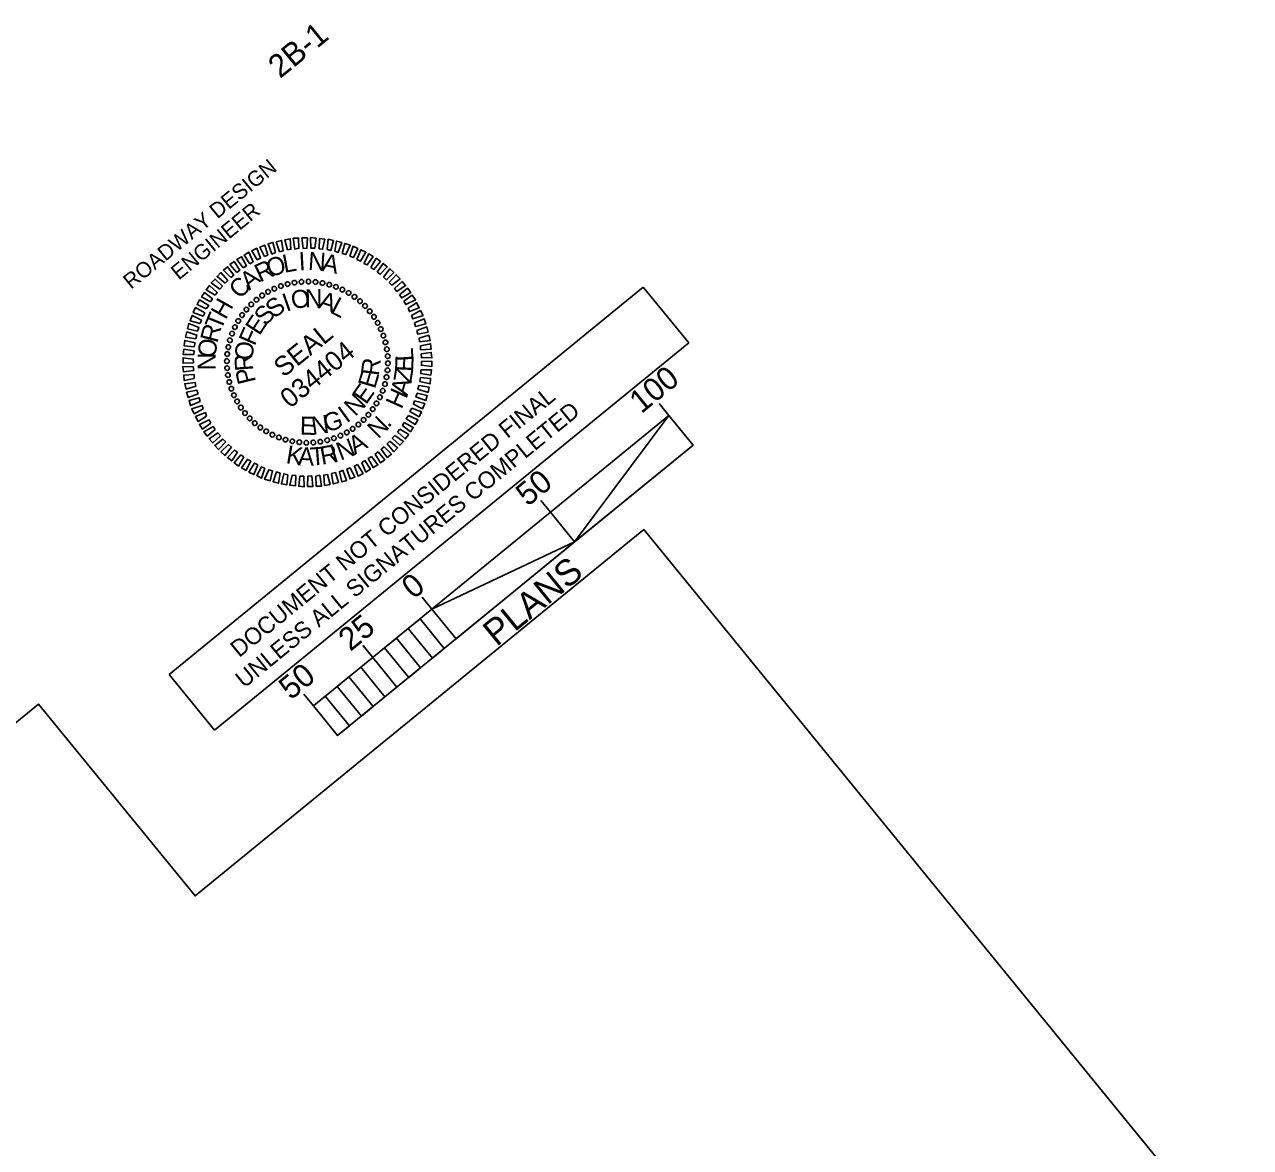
# Model space of a CAD drawing. Extents: x 1528967 to 2322919, y 597128 to 795043.
# Drawn here: x 2322186.2 to 2322586.9, y 598460.6 to 598827.5 of the extents above; entities that cross this region are included whole.
import ezdxf

# ---------------------------------------------------------------- set-up
doc = ezdxf.new("R2010")
doc.units = 0
for name, color, linetype in [('Sheet Data Field CELL', 7, 'Continuous'), ('Sheet Plan CELL', 7, 'Continuous'), ('Sheet Sticker Exception Certification CELL', 7, 'Continuous'), ('Sheet Title CELL', 7, 'Continuous')]:
    doc.layers.add(name, color=color, linetype=linetype)

msp = doc.modelspace()

# ---------------------------------------------------------------- linework, layer by layer
at = {"layer": 'Sheet Data Field CELL'}
for p, q in [((2322272.18, 598742.73), (2322272.18, 598742.73)), ((2322274.42, 598743.25), (2322274.42, 598743.25)), ((2322276.71, 598743.47), (2322276.71, 598743.47)), ((2322279.03, 598743.57), (2322279.03, 598743.57)), ((2322281.29, 598743.42), (2322281.29, 598743.42)), ((2322283.61, 598743.12), (2322283.61, 598743.12)), ((2322285.79, 598742.56), (2322285.79, 598742.56)), ((2322263.87, 598738.99), (2322263.87, 598738.99)), ((2322265.83, 598740.17), (2322265.83, 598740.17)), ((2322267.81, 598741.23), (2322267.81, 598741.23)), ((2322269.97, 598742.09), (2322269.97, 598742.09)), ((2322288, 598741.82), (2322288, 598741.82)), ((2322290.12, 598740.93), (2322290.12, 598740.93)), ((2322292.12, 598739.87), (2322292.12, 598739.87)), ((2322294.02, 598738.6), (2322294.02, 598738.6)), ((2322260.27, 598736.09), (2322260.27, 598736.09)), ((2322262, 598737.62), (2322262, 598737.62)), ((2322295.84, 598737.11), (2322295.84, 598737.11)), ((2322297.53, 598735.59), (2322297.53, 598735.59)), ((2322255.99, 598730.68), (2322255.99, 598730.68)), ((2322257.26, 598732.58), (2322257.26, 598732.58)), ((2322258.75, 598734.39), (2322258.75, 598734.39)), ((2322299.06, 598733.86), (2322299.06, 598733.86)), ((2322300.43, 598731.99), (2322300.43, 598731.99)), ((2322254.04, 598726.56), (2322254.04, 598726.56)), ((2322254.93, 598728.68), (2322254.93, 598728.68)), ((2322301.61, 598730.03), (2322301.61, 598730.03)), ((2322302.67, 598728.05), (2322302.67, 598728.05)), ((2322253.3, 598724.35), (2322253.3, 598724.35)), ((2322303.54, 598725.89), (2322303.54, 598725.89)), ((2322304.17, 598723.68), (2322304.17, 598723.68)), ((2322252.44, 598719.84), (2322252.44, 598719.84)), ((2322252.74, 598722.16), (2322252.74, 598722.16)), ((2322304.69, 598721.44), (2322304.69, 598721.44)), ((2322304.91, 598719.15), (2322304.91, 598719.15)), ((2322252.29, 598717.59), (2322252.29, 598717.59)), ((2322252.39, 598715.27), (2322252.39, 598715.27)), ((2322304.86, 598714.57), (2322304.86, 598714.57)), ((2322305.01, 598716.83), (2322305.01, 598716.83)), ((2322252.61, 598712.98), (2322252.61, 598712.98)), ((2322253.13, 598710.74), (2322253.13, 598710.74)), ((2322304.56, 598712.25), (2322304.56, 598712.25)), ((2322253.77, 598708.53), (2322253.77, 598708.53)), ((2322254.63, 598706.37), (2322254.63, 598706.37)), ((2322303.26, 598707.86), (2322303.26, 598707.86)), ((2322304, 598710.07), (2322304, 598710.07)), ((2322255.69, 598704.38), (2322255.69, 598704.38)), ((2322256.87, 598702.42), (2322256.87, 598702.42)), ((2322301.32, 598703.74), (2322301.32, 598703.74)), ((2322302.38, 598705.74), (2322302.38, 598705.74)), ((2322258.24, 598700.56), (2322258.24, 598700.56)), ((2322259.77, 598698.83), (2322259.77, 598698.83)), ((2322298.55, 598700.02), (2322298.55, 598700.02)), ((2322300.04, 598701.84), (2322300.04, 598701.84)), ((2322261.47, 598697.31), (2322261.47, 598697.31)), ((2322263.28, 598695.82), (2322263.28, 598695.82)), ((2322265.18, 598694.54), (2322265.18, 598694.54)), ((2322293.44, 598695.43), (2322293.44, 598695.43)), ((2322295.3, 598696.8), (2322295.3, 598696.8)), ((2322297.03, 598698.33), (2322297.03, 598698.33)), ((2322267.18, 598693.48), (2322267.18, 598693.48)), ((2322269.3, 598692.6), (2322269.3, 598692.6)), ((2322271.51, 598691.86), (2322271.51, 598691.86)), ((2322273.7, 598691.3), (2322273.7, 598691.3)), ((2322276.02, 598691), (2322276.02, 598691)), ((2322278.27, 598690.85), (2322278.27, 598690.85)), ((2322280.59, 598690.95), (2322280.59, 598690.95)), ((2322282.88, 598691.17), (2322282.88, 598691.17)), ((2322285.12, 598691.69), (2322285.12, 598691.69)), ((2322287.33, 598692.32), (2322287.33, 598692.32)), ((2322289.49, 598693.19), (2322289.49, 598693.19)), ((2322291.48, 598694.25), (2322291.48, 598694.25)), ((2322358.08, 598668.17), (2322354.92, 598672.03)), ((2322299.99, 598620.72), (2322296.83, 598624.59)), ((2322280.62, 598604.92), (2322277.46, 598608.78))]:
    msp.add_line(p, q, dxfattribs=at)
for points in [[(2322264.63, 598751.74), (2322263.13, 598754.73), (2322264.71, 598755.38), (2322265.71, 598752.17)], [(2322267.04, 598752.54), (2322265.83, 598755.84), (2322267.36, 598756.31), (2322268.2, 598753.04)], [(2322269.49, 598753.3), (2322268.49, 598756.51), (2322270.21, 598757), (2322270.74, 598753.61)], [(2322272.11, 598753.94), (2322271.26, 598757.14), (2322273.04, 598757.47), (2322273.28, 598754.1)], [(2322274.59, 598754.18), (2322274.03, 598757.69), (2322275.78, 598757.73), (2322275.88, 598754.45)], [(2322277.25, 598754.37), (2322276.87, 598757.82), (2322278.65, 598757.82), (2322278.48, 598754.45)], [(2322279.82, 598754.41), (2322279.7, 598757.89), (2322281.48, 598757.74), (2322281.09, 598754.46)], [(2322282.45, 598754.23), (2322282.58, 598757.57), (2322284.35, 598757.42), (2322283.59, 598754.1)], [(2322285.07, 598753.98), (2322285.39, 598757.34), (2322287.14, 598756.97), (2322286.31, 598753.65)], [(2322287.59, 598753.43), (2322288.13, 598756.77), (2322289.88, 598756.25), (2322288.72, 598753.08)], [(2322290.02, 598752.67), (2322290.86, 598755.99), (2322292.64, 598755.43), (2322291.26, 598752.34)], [(2322292.56, 598751.79), (2322293.61, 598755.09), (2322295.18, 598754.29), (2322293.68, 598751.43)], [(2322257.66, 598748.04), (2322255.62, 598750.78), (2322257.14, 598751.65), (2322258.76, 598748.69)], [(2322259.85, 598749.34), (2322258.04, 598752.21), (2322259.54, 598753.13), (2322260.92, 598750.04)], [(2322262.27, 598750.63), (2322260.47, 598753.57), (2322262.1, 598754.4), (2322263.28, 598751.14)], [(2322294.81, 598750.74), (2322296.16, 598753.94), (2322297.77, 598753.1), (2322295.96, 598750.2)], [(2322297.13, 598749.47), (2322298.69, 598752.58), (2322300.18, 598751.71), (2322298.24, 598748.97)], [(2322299.4, 598748.09), (2322301.18, 598751.18), (2322302.54, 598750.06), (2322300.39, 598747.49)], [(2322251.76, 598742.98), (2322249.16, 598745.17), (2322250.38, 598746.48), (2322252.62, 598743.91)], [(2322253.6, 598744.88), (2322251.19, 598747.31), (2322252.55, 598748.39), (2322254.59, 598745.65)], [(2322255.55, 598746.46), (2322253.35, 598749.07), (2322254.71, 598750.14), (2322256.55, 598747.24)], [(2322301.5, 598746.57), (2322303.38, 598749.47), (2322304.77, 598748.31), (2322302.45, 598745.94)], [(2322303.49, 598744.95), (2322305.62, 598747.72), (2322306.89, 598746.46), (2322304.46, 598744.13)], [(2322250.04, 598741.11), (2322247.24, 598743.14), (2322248.46, 598744.37), (2322250.9, 598742.05)], [(2322305.36, 598743.24), (2322307.69, 598745.76), (2322308.92, 598744.46), (2322306.25, 598742.34)], [(2322307.09, 598741.27), (2322309.59, 598743.59), (2322310.74, 598742.23), (2322307.9, 598740.31)], [(2322247.01, 598736.9), (2322244.06, 598738.52), (2322245, 598739.93), (2322247.62, 598737.89)], [(2322248.49, 598739.05), (2322245.52, 598740.86), (2322246.64, 598742.29), (2322249.17, 598739.96)], [(2322308.74, 598739.23), (2322311.42, 598741.35), (2322312.45, 598739.96), (2322309.48, 598738.2)], [(2322310.17, 598737.14), (2322312.94, 598739.07), (2322313.93, 598737.57), (2322310.78, 598736.01)], [(2322244.54, 598732.27), (2322241.36, 598733.43), (2322242.13, 598735.04), (2322245.12, 598733.37)], [(2322245.59, 598734.6), (2322242.59, 598736.04), (2322243.38, 598737.54), (2322246.39, 598735.69)], [(2322311.58, 598734.82), (2322314.33, 598736.6), (2322315.2, 598735.01), (2322311.97, 598733.71)], [(2322243.63, 598729.85), (2322240.32, 598730.76), (2322241.02, 598732.45), (2322243.99, 598730.97)], [(2322312.68, 598732.46), (2322315.61, 598734.04), (2322316.45, 598732.48), (2322313.08, 598731.35)], [(2322313.71, 598730.03), (2322316.8, 598731.41), (2322317.33, 598729.73), (2322313.98, 598728.82)], [(2322242.21, 598724.87), (2322238.86, 598725.33), (2322239.23, 598727.09), (2322242.53, 598726.03)], [(2322242.72, 598727.36), (2322239.51, 598728.15), (2322239.9, 598729.79), (2322243.19, 598728.58)], [(2322314.4, 598727.59), (2322317.66, 598728.77), (2322318.11, 598727.02), (2322314.74, 598726.37)], [(2322241.66, 598722.27), (2322238.41, 598722.54), (2322238.55, 598724.32), (2322241.95, 598723.47)], [(2322315.16, 598725.07), (2322318.29, 598726), (2322318.74, 598724.25), (2322315.32, 598723.9)], [(2322315.65, 598722.53), (2322318.91, 598723.23), (2322319.06, 598721.43), (2322315.62, 598721.27)], [(2322241.41, 598717.04), (2322238, 598716.84), (2322238, 598718.63), (2322241.36, 598718.24)], [(2322241.52, 598719.75), (2322238.09, 598719.66), (2322238.31, 598721.43), (2322241.62, 598720.93)], [(2322315.81, 598719.91), (2322319.12, 598720.38), (2322319.34, 598718.58), (2322315.93, 598718.71)], [(2322241.49, 598714.5), (2322238.18, 598714.04), (2322237.96, 598715.84), (2322241.37, 598715.7)], [(2322315.78, 598714.67), (2322319.21, 598714.75), (2322318.99, 598712.99), (2322315.68, 598713.49)], [(2322315.89, 598717.38), (2322319.3, 598717.58), (2322319.3, 598715.79), (2322315.94, 598716.18)], [(2322241.65, 598711.88), (2322238.39, 598711.19), (2322238.24, 598712.99), (2322241.68, 598713.15)], [(2322242.14, 598709.35), (2322239.01, 598708.42), (2322238.56, 598710.17), (2322241.98, 598710.52)], [(2322315.64, 598712.15), (2322318.9, 598711.88), (2322318.75, 598710.1), (2322315.36, 598710.94)], [(2322242.9, 598706.83), (2322239.64, 598705.65), (2322239.19, 598707.4), (2322242.56, 598708.05)], [(2322314.58, 598707.06), (2322317.8, 598706.27), (2322317.4, 598704.63), (2322314.11, 598705.84)], [(2322315.09, 598709.55), (2322318.44, 598709.09), (2322318.07, 598707.33), (2322314.77, 598708.39)], [(2322243.59, 598704.39), (2322240.5, 598703.01), (2322239.97, 598704.69), (2322243.32, 598705.6)], [(2322244.62, 598701.96), (2322241.69, 598700.38), (2322240.86, 598701.94), (2322244.23, 598703.07)], [(2322313.67, 598704.57), (2322316.98, 598703.66), (2322316.28, 598701.97), (2322313.32, 598703.44)], [(2322245.72, 598699.59), (2322242.97, 598697.81), (2322242.1, 598699.41), (2322245.33, 598700.71)], [(2322247.13, 598697.28), (2322244.36, 598695.35), (2322243.37, 598696.85), (2322246.52, 598698.41)], [(2322311.71, 598699.82), (2322314.72, 598698.38), (2322313.92, 598696.88), (2322310.91, 598698.73)], [(2322312.76, 598702.15), (2322315.94, 598700.99), (2322315.17, 598699.38), (2322312.18, 598701.05)], [(2322248.56, 598695.19), (2322245.89, 598693.07), (2322244.85, 598694.46), (2322247.82, 598696.22)], [(2322308.81, 598695.37), (2322311.78, 598693.56), (2322310.66, 598692.13), (2322308.14, 598694.46)], [(2322310.29, 598697.52), (2322313.24, 598695.89), (2322312.31, 598694.48), (2322309.68, 598696.53)], [(2322250.21, 598693.15), (2322247.71, 598690.83), (2322246.56, 598692.19), (2322249.4, 598694.11)], [(2322251.95, 598691.18), (2322249.61, 598688.66), (2322248.38, 598689.95), (2322251.05, 598692.08)], [(2322305.54, 598691.44), (2322308.15, 598689.25), (2322306.92, 598687.93), (2322304.68, 598690.5)], [(2322307.26, 598693.3), (2322310.07, 598691.28), (2322308.85, 598690.04), (2322306.4, 598692.37)], [(2322253.81, 598689.46), (2322251.68, 598686.7), (2322250.41, 598687.96), (2322252.84, 598690.29)], [(2322255.8, 598687.85), (2322253.92, 598684.95), (2322252.53, 598686.11), (2322254.85, 598688.48)], [(2322257.91, 598686.33), (2322256.12, 598683.24), (2322254.76, 598684.36), (2322256.91, 598686.93)], [(2322299.64, 598686.38), (2322301.69, 598683.64), (2322300.16, 598682.76), (2322298.55, 598685.73)], [(2322301.75, 598687.96), (2322303.95, 598685.35), (2322302.59, 598684.27), (2322300.75, 598687.18)], [(2322303.7, 598689.54), (2322306.11, 598687.11), (2322304.75, 598686.03), (2322302.71, 598688.77)], [(2322260.17, 598684.95), (2322258.61, 598681.84), (2322257.12, 598682.71), (2322259.06, 598685.45)], [(2322262.49, 598683.68), (2322261.14, 598680.47), (2322259.54, 598681.32), (2322261.34, 598684.22)], [(2322264.75, 598682.63), (2322263.69, 598679.33), (2322262.12, 598680.13), (2322263.62, 598682.99)], [(2322292.67, 598682.68), (2322294.17, 598679.69), (2322292.59, 598679.04), (2322291.59, 598682.25)], [(2322295.03, 598683.79), (2322296.84, 598680.85), (2322295.2, 598680.01), (2322294.02, 598683.28)], [(2322297.45, 598685.08), (2322299.26, 598682.21), (2322297.77, 598681.29), (2322296.39, 598684.38)], [(2322267.28, 598681.75), (2322266.44, 598678.43), (2322264.66, 598678.99), (2322266.04, 598682.08)], [(2322269.71, 598680.99), (2322269.17, 598677.65), (2322267.43, 598678.16), (2322268.58, 598681.34)], [(2322272.23, 598680.44), (2322271.91, 598677.08), (2322270.16, 598677.45), (2322270.99, 598680.77)], [(2322274.85, 598680.19), (2322274.72, 598676.85), (2322272.95, 598676.99), (2322273.71, 598680.32)], [(2322277.48, 598680), (2322277.6, 598676.53), (2322275.83, 598676.68), (2322276.21, 598679.96)], [(2322280.05, 598680.05), (2322280.44, 598676.59), (2322278.65, 598676.59), (2322278.82, 598679.97)], [(2322282.71, 598680.24), (2322283.28, 598676.73), (2322281.52, 598676.69), (2322281.42, 598679.97)], [(2322285.19, 598680.48), (2322286.04, 598677.28), (2322284.26, 598676.94), (2322284.02, 598680.31)], [(2322287.81, 598681.11), (2322288.81, 598677.9), (2322287.09, 598677.42), (2322286.56, 598680.81)], [(2322290.26, 598681.88), (2322291.47, 598678.58), (2322289.94, 598678.11), (2322289.1, 598681.38)]]:
    msp.add_lwpolyline(points, close=True, dxfattribs=at)
for centre, major_axis in [((2322269.98, 598742.06), (-0.249, 0.713)), ((2322272.18, 598742.72), (-0.186, 0.732)), ((2322274.43, 598743.19), (-0.121, 0.746)), ((2322276.71, 598743.45), (-0.056, 0.753)), ((2322279.01, 598743.52), (0.01, 0.755)), ((2322281.3, 598743.39), (0.076, 0.752)), ((2322283.57, 598743.06), (0.141, 0.742)), ((2322285.8, 598742.54), (0.205, 0.727)), ((2322287.98, 598741.82), (0.268, 0.706)), ((2322262.01, 598737.59), (-0.478, 0.585)), ((2322263.85, 598738.97), (-0.425, 0.625)), ((2322265.8, 598740.18), (-0.369, 0.659)), ((2322267.85, 598741.21), (-0.31, 0.689)), ((2322290.09, 598740.91), (0.328, 0.68)), ((2322292.11, 598739.82), (0.387, 0.649)), ((2322294.03, 598738.56), (0.442, 0.613)), ((2322258.72, 598734.39), (-0.572, 0.493)), ((2322260.29, 598736.07), (-0.527, 0.541)), ((2322295.84, 598737.14), (0.493, 0.572)), ((2322297.51, 598735.57), (0.541, 0.527)), ((2322299.04, 598733.85), (0.585, 0.478)), ((2322256.04, 598730.67), (-0.649, 0.387)), ((2322257.3, 598732.59), (-0.613, 0.442)), ((2322300.41, 598732.01), (0.625, 0.425)), ((2322301.62, 598730.06), (0.659, 0.369)), ((2322254.04, 598726.54), (-0.706, 0.268)), ((2322254.95, 598728.65), (-0.68, 0.328)), ((2322302.65, 598728.01), (0.689, 0.31)), ((2322303.5, 598725.88), (0.713, 0.249)), ((2322252.8, 598722.13), (-0.742, 0.141)), ((2322253.32, 598724.36), (-0.727, 0.205)), ((2322304.16, 598723.68), (0.732, 0.186)), ((2322252.47, 598719.86), (-0.752, 0.076)), ((2322304.63, 598721.43), (0.746, 0.121)), ((2322304.9, 598719.15), (0.753, 0.056)), ((2322252.34, 598717.56), (-0.755, 0.01)), ((2322252.41, 598715.27), (-0.753, -0.056)), ((2322304.83, 598714.56), (0.752, -0.076)), ((2322304.97, 598716.85), (0.755, -0.01)), ((2322252.67, 598712.99), (-0.746, -0.121)), ((2322253.14, 598710.74), (-0.732, -0.186)), ((2322303.98, 598710.06), (0.727, -0.205)), ((2322304.5, 598712.29), (0.742, -0.141)), ((2322253.8, 598708.54), (-0.713, -0.249)), ((2322254.65, 598706.41), (-0.689, -0.31)), ((2322302.35, 598705.77), (0.68, -0.328)), ((2322303.26, 598707.88), (0.706, -0.268)), ((2322255.68, 598704.36), (-0.659, -0.369)), ((2322256.89, 598702.41), (-0.625, -0.425)), ((2322300, 598701.83), (0.613, -0.442)), ((2322301.26, 598703.74), (0.649, -0.387)), ((2322258.27, 598700.57), (-0.585, -0.478)), ((2322259.79, 598698.85), (-0.541, -0.527)), ((2322297.01, 598698.35), (0.527, -0.541)), ((2322298.58, 598700.02), (0.572, -0.493)), ((2322261.46, 598697.28), (-0.493, -0.572)), ((2322263.27, 598695.86), (-0.442, -0.613)), ((2322265.19, 598694.6), (-0.387, -0.649)), ((2322267.21, 598693.51), (-0.328, -0.68)), ((2322291.5, 598694.24), (0.369, -0.659)), ((2322293.45, 598695.45), (0.425, -0.625)), ((2322295.29, 598696.82), (0.478, -0.585)), ((2322269.32, 598692.6), (-0.268, -0.706)), ((2322271.5, 598691.88), (-0.205, -0.727)), ((2322273.73, 598691.36), (-0.141, -0.742)), ((2322276, 598691.03), (-0.076, -0.752)), ((2322278.3, 598690.89), (-0.01, -0.755)), ((2322280.59, 598690.96), (0.056, -0.753)), ((2322282.87, 598691.23), (0.121, -0.746)), ((2322285.12, 598691.7), (0.186, -0.732)), ((2322287.32, 598692.36), (0.249, -0.713)), ((2322289.45, 598693.21), (0.31, -0.689))]:
    msp.add_ellipse(centre, major_axis=major_axis, ratio=0.999708, dxfattribs=at)
at = {"layer": 'Sheet Plan CELL'}
msp.add_lwpolyline([(2321170.32, 597940.94), (2321932.56, 598563.23), (2321956.07, 598534.43), (2322069.68, 598627.18), (2322128.74, 598554.85), (2322190.77, 598605.49), (2322241.95, 598542.8), (2322388.56, 598662.49), (2322586.87, 598419.63), (2321502.31, 597534.26)], close=True, dxfattribs=at)
at = {"layer": 'Sheet Sticker Exception Certification CELL'}
for p, q in [((2322233.48, 598615.21), (2322388.43, 598741.72)), ((2322388.44, 598741.71), (2322403.3, 598723.5)), ((2322403.29, 598723.51), (2322248.34, 598597.01)), ((2322248.34, 598597.01), (2322233.48, 598615.21))]:
    msp.add_line(p, q, dxfattribs=at)
at = {"layer": 'Sheet Title CELL'}
for p, q in [((2322396.8, 598699.77), (2322393.64, 598703.65)), ((2322396.8, 598699.77), (2322280.62, 598604.9)), ((2322288.52, 598595.22), (2322404.72, 598690.08)), ((2322358.08, 598668.15), (2322354.92, 598672.01)), ((2322358.08, 598668.15), (2322365.98, 598658.47)), ((2322319.35, 598636.52), (2322316.19, 598640.39)), ((2322307.73, 598627.04), (2322315.63, 598617.36)), ((2322299.99, 598620.7), (2322296.82, 598624.59)), ((2322280.62, 598604.9), (2322277.46, 598608.77)), ((2322277.46, 598608.77), (2322277.46, 598608.77))]:
    msp.add_line(p, q, dxfattribs=at)
for points in [[(2322396.8, 598699.77), (2322365.98, 598658.47), (2322404.72, 598690.08)], [(2322319.35, 598636.52), (2322365.98, 598658.47), (2322327.26, 598626.83)], [(2322311.6, 598630.2), (2322315.47, 598633.36), (2322323.39, 598623.67), (2322319.51, 598620.52)], [(2322303.86, 598623.87), (2322307.73, 598627.04), (2322315.63, 598617.36), (2322311.76, 598614.19)], [(2322296.12, 598617.54), (2322299.99, 598620.7), (2322307.89, 598611.03), (2322304.01, 598607.87)], [(2322288.36, 598611.23), (2322292.24, 598614.38), (2322300.15, 598604.7), (2322296.29, 598601.54)], [(2322280.62, 598604.9), (2322284.49, 598608.06), (2322292.4, 598598.38), (2322288.52, 598595.22)]]:
    msp.add_lwpolyline(points, close=True, dxfattribs=at)

# ---------------------------------------------------------------- texts
at = {"layer": 'Sheet Data Field CELL'}
for s, height, rotation, p in [('2B-1', 7.5, 39.228, (2322269.72, 598809.68)), ('O', 5.92, 17.6498, (2322266.33, 598744.86)), ('L', 5.92, 10.4495, (2322271.11, 598746.36)), ('I', 5.92, 3.2488, (2322275.98, 598747.18)), ('N', 5.92, 356.0476, (2322278.75, 598747.39)), ('A', 5.92, 348.8458, (2322283.11, 598747.03)), ('A', 5.92, 39.249, (2322259.64, 598740.5)), ('R', 5.92, 24.8497, (2322263.14, 598743.19)), ('C', 5.92, 46.4485, (2322256.67, 598737.58)), ('I', 5.92, 19.4182, (2322271.76, 598733.64)), ('O', 5.92, 10.0621, (2322273.83, 598734.44)), ('N', 5.92, 0.7053, (2322277.87, 598735.11)), ('A', 5.92, 341.9889, (2322281.92, 598734.95)), ('L', 5.92, 332.6295, (2322285.82, 598733.51)), ('H', 5.92, 60.8481, (2322251.94, 598730.83)), ('S', 5.92, 47.4843, (2322264.99, 598728.81)), ('S', 5.92, 38.129, (2322267.84, 598731.29)), ('T', 5.92, 68.0484, (2322250.46, 598727.31)), ('E', 5.92, 56.8397, (2322262.94, 598725.63)), ('R', 5.92, 75.2491, (2322249.22, 598723.24)), ('F', 5.91, 66.1957, (2322261.39, 598722.26)), ('SEAL', 6.294, 39.2286, (2322270.88, 598712.01)), ('O', 5.92, 82.4504, (2322248.56, 598718.42)), ('O', 5.92, 84.9099, (2322260.74, 598717.66)), ('034404', 6.296, 39.2286, (2322272.98, 598701.91)), ('N', 5.92, 89.6521, (2322248.68, 598714.54)), ('R', 5.92, 94.2683, (2322261, 598714.51)), ('E', 5.92, 87.3529, (2322313.17, 598713.97)), ('L', 5.92, 93.5277, (2322313.36, 598717.65)), ('P', 5.92, 103.6275, (2322261.89, 598710.86)), ('E', 5.92, 73.3527, (2322300.72, 598708.26)), ('R', 5.92, 82.7101, (2322301.98, 598712.54)), ('Z', 5.92, 80.8134, (2322312.53, 598710.11)), ('100', 7.5, 39.2328, (2322387.78, 598700.17)), ('E', 5.92, 54.6404, (2322297.8, 598703.1)), ('A', 5.92, 73.5637, (2322311.32, 598705.96)), ('N', 5.92, 45.285, (2322294.24, 598699.27)), ('H', 5.92, 65.6038, (2322309.4, 598701.62)), ('I', 5.92, 35.9298, (2322291.46, 598697.12)), ('E', 5.92, 358.5055, (2322276.12, 598693.56)), ('N', 5.92, 7.8626, (2322280.35, 598693.43)), ('G', 5.92, 17.2189, (2322284.92, 598694.2)), ('N', 5.92, 44.824, (2322301.76, 598691.92)), ('.', 5.92, 53.2446, (2322305.28, 598695.51)), ('I', 5.92, 16.9385, (2322287.12, 598684.32)), ('N', 5.92, 21.0594, (2322289.49, 598684.98)), ('A', 5.92, 29.48, (2322294.16, 598686.85)), ('K', 5.92, 350.3966, (2322271.41, 598684.26)), ('A', 5.92, 357.3008, (2322275.47, 598683.58)), ('T', 5.92, 4.5505, (2322279.8, 598683.38)), ('R', 5.92, 10.5334, (2322283.36, 598683.64)), ('50', 7.5, 39.2328, (2322350.66, 598669.84)), ('25', 7.5, 39.2328, (2322292.69, 598622.5)), ('50', 7.5, 39.2328, (2322273.21, 598606.6))]:
    msp.add_text(s, height=height, rotation=rotation, dxfattribs=at).set_placement(p)
at = {"layer": 'Sheet Plan CELL'}
for s, height, p in [('ROADWAY DESIGN', 5.0001, (2322221.02, 598740.83)), ('ENGINEER', 5, (2322236.62, 598743.84))]:
    msp.add_text(s, height=height, rotation=39.228, dxfattribs=at).set_placement(p)
at = {"layer": 'Sheet Sticker Exception Certification CELL'}
for s, p in [('DOCUMENT NOT CONSIDERED FINAL', (2322256.34, 598620.52)), ('UNLESS ALL SIGNATURES COMPLETED', (2322257.98, 598610.5))]:
    msp.add_text(s, height=5.5, rotation=39.228, dxfattribs=at).set_placement(p)
at = {"layer": 'Sheet Title CELL'}
for s, height, p in [('PLANS', 8.5, (2322340.49, 598624.08)), ('0', 7.5, (2322313.33, 598639.54))]:
    msp.add_text(s, height=height, rotation=39.2328, dxfattribs=at).set_placement(p)

doc.saveas('drawing.dxf')
